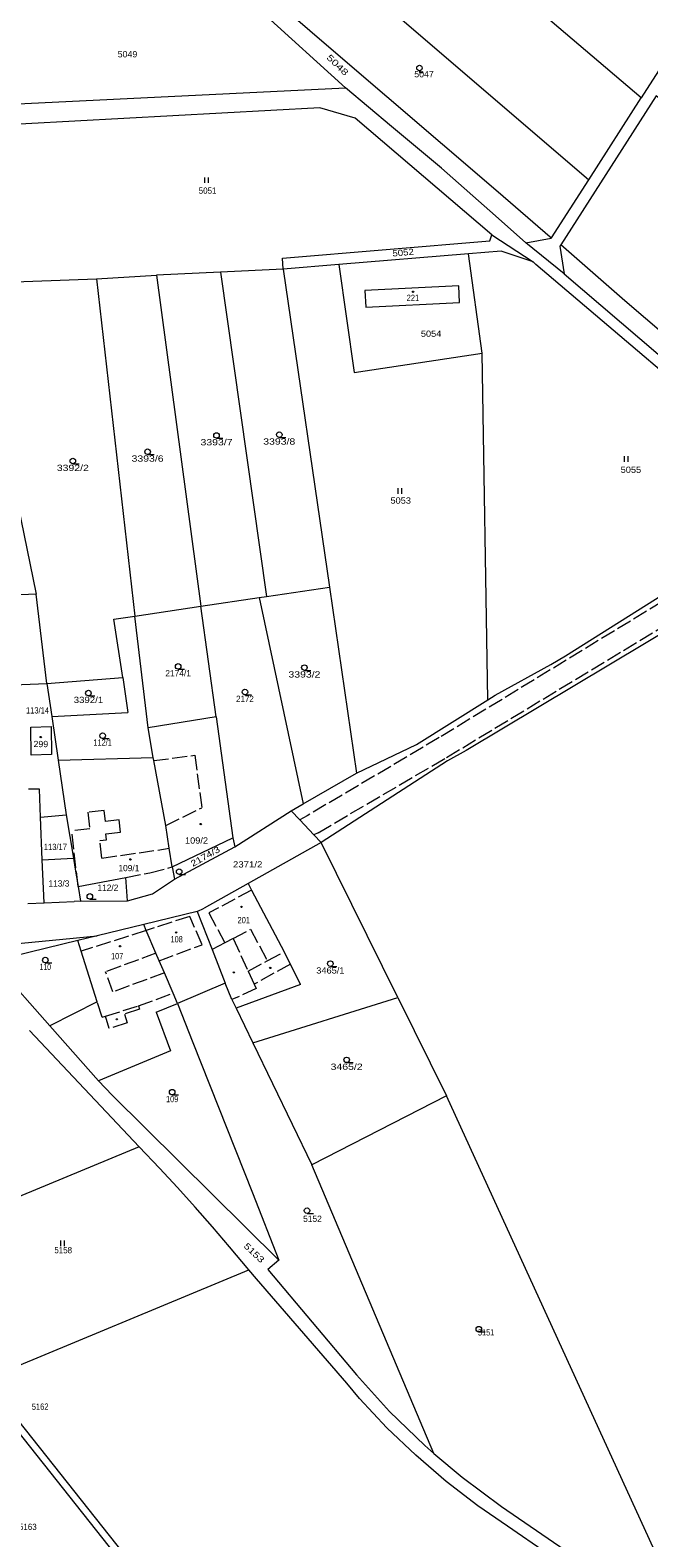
# Model space of a CAD drawing. Extents: x -590528 to -586543, y -1119609 to -1116685.
# Drawn here: x -588531 to -588363.1, y -1118530.4 to -1118121.8 of the extents above; entities that cross this region are included whole.
import ezdxf
from ezdxf.enums import TextEntityAlignment as Align

# ---------------------------------------------------------------- set-up
doc = ezdxf.new("R2010")
doc.units = 0
doc.header["$LTSCALE"] = 0.68
doc.linetypes.add('LONG_DASHED', pattern=[7.5, 6, -1.5])
for name, color, linetype, lineweight in [('1', 7, 'Continuous', 13), ('2', 7, 'LONG_DASHED', 13), ('3', 7, 'Continuous', 13), ('6', 7, 'Continuous', 13)]:
    doc.layers.add(name, color=color, linetype=linetype, lineweight=lineweight)

msp = doc.modelspace()

# ---------------------------------------------------------------- linework, layer by layer
at = {"layer": '1'}
for p, q in [((-588306.86, -1118049.02), (-588365.16, -1118140.1)), ((-588365.16, -1118140.1), (-588458.27, -1118060.91)), ((-588463.5, -1118090.17), (-588379.4, -1118162.35)), ((-588445.35, -1118137.46), (-588467.73, -1118117.14)), ((-588562.14, -1118143.12), (-588445.35, -1118137.46)), ((-588432.86, -1118147.9), (-588445.35, -1118137.46)), ((-588379.4, -1118162.35), (-588365.16, -1118140.1)), ((-588405.64, -1118177.25), (-588442.78, -1118145.68)), ((-588403.93, -1118165.64), (-588389.82, -1118177.8)), ((-588405.64, -1118177.25), (-588394.44, -1118184.61)), ((-588386.08, -1118187.86), (-588396.42, -1118179.44)), ((-588479.32, -1118187.36), (-588466.79, -1118275.29)), ((-588447.22, -1118185.31), (-588462.32, -1118186.55)), ((-588462.32, -1118186.55), (-588449.74, -1118272.77)), ((-588512.93, -1118189.15), (-588496.67, -1118188.18)), ((-588512.93, -1118189.15), (-588502.58, -1118280.59)), ((-588496.67, -1118188.18), (-588484.64, -1118277.93)), ((-588406.8, -1118303.29), (-588408.31, -1118209.31)), ((-588534.32, -1118250.35), (-588529.35, -1118274.66)), ((-588529.35, -1118274.66), (-588568.79, -1118276.37)), ((-588526.42, -1118298.88), (-588529.35, -1118274.66)), ((-588468.82, -1118275.59), (-588456.87, -1118331.51)), ((-588480.5, -1118307.9), (-588484.64, -1118277.93)), ((-588350.37, -1118279.8), (-588412.67, -1118317.05)), ((-588526.42, -1118298.88), (-588505.84, -1118297.29)), ((-588505.84, -1118297.29), (-588504.42, -1118306.75)), ((-588526.42, -1118298.88), (-588525.11, -1118307.78)), ((-588525.11, -1118307.78), (-588504.42, -1118306.75)), ((-588525.11, -1118307.78), (-588523.38, -1118319.65)), ((-588480.5, -1118307.9), (-588475.97, -1118340.68)), ((-588530.66, -1118318.29), (-588530.75, -1118310.67)), ((-588497.59, -1118318.95), (-588498.89, -1118310.86)), ((-588525.16, -1118318.1), (-588530.66, -1118318.29)), ((-588412.67, -1118317.05), (-588417.72, -1118319.86)), ((-588523.38, -1118319.65), (-588497.59, -1118318.95)), ((-588523.38, -1118319.65), (-588521.18, -1118334.51)), ((-588417.72, -1118319.86), (-588452.02, -1118342.01)), ((-588456.87, -1118331.51), (-588442.39, -1118323.14)), ((-588528.46, -1118327.49), (-588531.44, -1118327.55)), ((-588475.44, -1118343.19), (-588460.12, -1118333.39)), ((-588460.12, -1118333.39), (-588456.87, -1118331.51)), ((-588460.12, -1118333.39), (-588457.79, -1118335.87)), ((-588493.2, -1118343.55), (-588494.13, -1118337.39)), ((-588457.79, -1118335.87), (-588453.97, -1118339.94)), ((-588492.43, -1118348.6), (-588475.97, -1118340.68)), ((-588475.97, -1118340.68), (-588475.44, -1118343.19)), ((-588453.97, -1118339.94), (-588452.02, -1118342.01)), ((-588431.15, -1118384.02), (-588452.02, -1118342.01)), ((-588527.67, -1118346.7), (-588519.23, -1118346.22)), ((-588527.19, -1118358.3), (-588527.67, -1118346.7)), ((-588492.43, -1118348.6), (-588493.2, -1118343.55)), ((-588491.8, -1118351.95), (-588475.44, -1118343.19)), ((-588518.83, -1118348.62), (-588517.95, -1118353.91)), ((-588492.43, -1118348.6), (-588491.8, -1118351.95)), ((-588517.95, -1118353.91), (-588505.03, -1118351.45)), ((-588504.56, -1118357.77), (-588505.03, -1118351.45)), ((-588497.78, -1118355.9), (-588491.8, -1118351.95)), ((-588471.83, -1118353.1), (-588470.87, -1118354.91)), ((-588470.87, -1118354.91), (-588462.02, -1118371.6)), ((-588517.29, -1118357.9), (-588518.99, -1118357.97)), ((-588504.56, -1118357.77), (-588497.78, -1118355.9)), ((-588485.61, -1118360.7), (-588500.14, -1118364.23)), ((-588485.61, -1118360.7), (-588483.71, -1118359.75)), ((-588485.61, -1118360.7), (-588481.59, -1118371.02)), ((-588544.65, -1118370.34), (-588512.81, -1118367.3)), ((-588518.04, -1118368.57), (-588541.12, -1118374.2)), ((-588517.13, -1118371.44), (-588518.04, -1118368.57)), ((-588512.79, -1118385.12), (-588517.13, -1118371.44)), ((-588481.59, -1118371.02), (-588478.06, -1118380.09)), ((-588541.12, -1118374.2), (-588525.61, -1118391.67)), ((-588460.34, -1118374.98), (-588462.02, -1118371.6)), ((-588457.62, -1118380.46), (-588460.34, -1118374.98)), ((-588490.96, -1118385.61), (-588492.15, -1118382.84)), ((-588457.62, -1118380.46), (-588475.09, -1118386.9)), ((-588512.79, -1118385.12), (-588525.61, -1118391.67)), ((-588496.73, -1118387.95), (-588490.96, -1118385.61)), ((-588476.23, -1118384.56), (-588475.09, -1118386.9)), ((-588431.15, -1118384.02), (-588417.94, -1118410.63)), ((-588525.61, -1118391.67), (-588512.39, -1118406.56)), ((-588531.17, -1118392.89), (-588501.37, -1118424.43)), ((-588486.77, -1118396.19), (-588470.63, -1118436.94)), ((-588470.55, -1118396.26), (-588454.52, -1118429.35)), ((-588508.68, -1118410.46), (-588512.39, -1118406.56)), ((-588463.48, -1118455.16), (-588508.68, -1118410.46)), ((-588417.94, -1118410.63), (-588454.52, -1118429.35)), ((-588354.11, -1118550.09), (-588417.94, -1118410.63)), ((-588470.63, -1118436.94), (-588463.48, -1118455.16)), ((-588544.44, -1118488.93), (-588490.36, -1118556.97)), ((-588492.66, -1118550.88), (-588543.11, -1118487.4)), ((-588421.41, -1118507.55), (-588413.75, -1118514.03)), ((-588413.75, -1118514.03), (-588403.05, -1118521.93))]:
    msp.add_line(p, q, dxfattribs=at)
for points in [[(-588467.28, -1118111.3), (-588449.24, -1118126.81), (-588403.93, -1118165.64)], [(-588273.64, -1118212.52), (-588361.09, -1118139.58), (-588386.98, -1118180.02)], [(-588442.78, -1118145.68), (-588452.37, -1118142.81), (-588545.5, -1118147.9)], [(-588396.42, -1118179.44), (-588404.65, -1118172.16), (-588419.38, -1118159.23), (-588432.86, -1118147.9)], [(-588389.82, -1118177.8), (-588389.47, -1118178.07), (-588379.4, -1118162.35)], [(-588462.32, -1118186.55), (-588462.46, -1118183.55), (-588406.2, -1118178.91), (-588405.64, -1118177.25)], [(-588396.42, -1118179.44), (-588389.55, -1118178.2), (-588389.47, -1118178.07)], [(-588394.44, -1118184.61), (-588403.13, -1118181.67), (-588412.04, -1118182.4)], [(-588317.69, -1118239.25), (-588322.95, -1118234.85), (-588342.23, -1118218.58), (-588369.57, -1118195.12), (-588386.98, -1118180.02), (-588387.2, -1118180.36), (-588386.08, -1118187.86), (-588330.07, -1118235.65), (-588326.39, -1118238.65)], [(-588462.32, -1118186.55), (-588479.32, -1118187.36), (-588496.67, -1118188.18)], [(-588332.01, -1118237.68), (-588393.7, -1118185.27), (-588394.44, -1118184.61)], [(-588540.83, -1118187.61), (-588540.17, -1118190.18), (-588512.93, -1118189.15)], [(-588389.65, -1118293.69), (-588385.67, -1118291.34), (-588328.77, -1118255.57)], [(-588468.82, -1118275.59), (-588466.79, -1118275.29), (-588449.74, -1118272.77), (-588442.39, -1118323.14)], [(-588505.84, -1118297.29), (-588508.23, -1118281.43), (-588502.58, -1118280.59), (-588484.64, -1118277.93), (-588468.82, -1118275.59)], [(-588480.5, -1118307.9), (-588498.89, -1118310.86), (-588502.58, -1118280.59)], [(-588442.39, -1118323.14), (-588426.09, -1118315.45), (-588406.8, -1118303.29), (-588404.76, -1118302), (-588389.65, -1118293.69)], [(-588555.73, -1118299.98), (-588548.3, -1118299.69), (-588540.24, -1118299.39), (-588533.24, -1118299.13), (-588526.42, -1118298.88)], [(-588530.75, -1118310.67), (-588525.23, -1118310.52), (-588525.16, -1118318.1)], [(-588494.13, -1118337.39), (-588497.43, -1118319.79), (-588497.59, -1118318.95)], [(-588527.67, -1118346.7), (-588528.14, -1118335.08), (-588528.46, -1118327.49)], [(-588528.14, -1118335.08), (-588521.18, -1118334.51), (-588519.23, -1118346.22), (-588518.83, -1118348.62)], [(-588452.02, -1118342.01), (-588471.83, -1118353.1), (-588483.71, -1118359.75)], [(-588517.95, -1118353.91), (-588517.29, -1118357.9), (-588504.56, -1118357.77)], [(-588531.56, -1118358.48), (-588527.19, -1118358.3), (-588518.99, -1118357.97)], [(-588499.45, -1118365.83), (-588500.14, -1118364.23), (-588512.81, -1118367.3), (-588518.04, -1118368.57)], [(-588495.92, -1118374.06), (-588496.81, -1118371.98), (-588499.45, -1118365.83)], [(-588492.15, -1118382.84), (-588494.52, -1118377.32), (-588495.92, -1118374.06)], [(-588476.23, -1118384.56), (-588478.06, -1118380.09), (-588490.96, -1118385.61), (-588486.77, -1118396.19)], [(-588475.09, -1118386.9), (-588470.55, -1118396.26), (-588431.15, -1118384.02)], [(-588496.73, -1118387.95), (-588492.9, -1118398.44), (-588512.39, -1118406.56)], [(-588501.37, -1118424.43), (-588569.89, -1118452.8), (-588586.49, -1118433.03)], [(-588543.11, -1118487.4), (-588471.59, -1118457.8), (-588476.86, -1118451.54), (-588481.49, -1118446.13), (-588486.19, -1118440.78), (-588490.97, -1118435.5), (-588495.83, -1118430.28), (-588501.37, -1118424.43)], [(-588433.45, -1118496.17), (-588423.9, -1118505.43), (-588421.41, -1118507.55), (-588454.52, -1118429.35)], [(-588463.48, -1118455.16), (-588466.46, -1118457.67), (-588442.36, -1118486.29), (-588433.45, -1118496.17)], [(-588418.08, -1118515.14), (-588426.3, -1118508.08), (-588434.13, -1118500.59), (-588441.55, -1118492.69), (-588445.01, -1118488.5), (-588469.51, -1118460.25), (-588471.59, -1118457.8)], [(-588403.05, -1118521.93), (-588379.49, -1118538.12), (-588366.48, -1118545.6), (-588361.01, -1118548.5), (-588355.05, -1118550.07), (-588354.11, -1118550.09), (-588348.89, -1118550.23), (-588342.86, -1118548.98), (-588328.2, -1118545.4), (-588227.19, -1118511.98)], [(-588401.4, -1118527.28), (-588409.5, -1118521.75), (-588418.08, -1118515.14)], [(-588226.11, -1118515.22), (-588341.38, -1118553.44), (-588344.14, -1118554.35), (-588349.91, -1118555.14), (-588355.73, -1118554.85), (-588361.39, -1118553.51), (-588366.71, -1118551.14), (-588369.11, -1118549.5), (-588401.4, -1118527.28)]]:
    msp.add_lwpolyline(points, dxfattribs=at)
for points in [[(-588408.31, -1118209.31), (-588412.04, -1118182.4), (-588447.22, -1118185.31), (-588443.02, -1118214.61)], [(-588414.67, -1118191.08), (-588440.13, -1118192.33), (-588439.91, -1118196.84), (-588414.45, -1118195.6)]]:
    msp.add_lwpolyline(points, close=True, dxfattribs=at)
at = {"layer": '2'}
for p, q in [((-588497.43, -1118319.79), (-588486.28, -1118318.33)), ((-588486.28, -1118318.33), (-588484.37, -1118332.54)), ((-588510.84, -1118333.27), (-588515.31, -1118333.77)), ((-588515.31, -1118333.77), (-588514.8, -1118338.25)), ((-588510.5, -1118336.25), (-588510.84, -1118333.27)), ((-588494.13, -1118337.39), (-588484.37, -1118332.54)), ((-588455.77, -1118334.72), (-588457.79, -1118335.87)), ((-588514.8, -1118338.25), (-588519.67, -1118338.8)), ((-588517.95, -1118353.91), (-588519.67, -1118338.8)), ((-588506.82, -1118335.83), (-588510.5, -1118336.25)), ((-588506.44, -1118339.21), (-588506.82, -1118335.83)), ((-588512.02, -1118341.45), (-588510.23, -1118341.25)), ((-588511.48, -1118346.22), (-588512.02, -1118341.45)), ((-588510.41, -1118339.66), (-588506.44, -1118339.21)), ((-588510.23, -1118341.25), (-588510.41, -1118339.66)), ((-588452.81, -1118339.31), (-588453.97, -1118339.94)), ((-588511.48, -1118346.22), (-588493.2, -1118343.55)), ((-588505.03, -1118351.45), (-588498.51, -1118350.21)), ((-588498.51, -1118350.21), (-588492.43, -1118348.6)), ((-588470.87, -1118354.91), (-588482.44, -1118361.04)), ((-588484.3, -1118369.68), (-588487.64, -1118361.99)), ((-588482.44, -1118361.04), (-588478.13, -1118369.17)), ((-588475.88, -1118367.97), (-588471.16, -1118365.47)), ((-588495.92, -1118374.06), (-588484.3, -1118369.68)), ((-588496.81, -1118371.98), (-588510.49, -1118377.01)), ((-588460.34, -1118374.98), (-588470.17, -1118380.37)), ((-588508.49, -1118382.45), (-588510.49, -1118377.01)), ((-588494.52, -1118377.32), (-588508.49, -1118382.45)), ((-588471.81, -1118376.82), (-588470.17, -1118380.37)), ((-588501.58, -1118386.23), (-588492.15, -1118382.84)), ((-588469.62, -1118381.57), (-588476.23, -1118384.56)), ((-588470.17, -1118380.37), (-588469.62, -1118381.57)), ((-588511.44, -1118389.36), (-588512.79, -1118385.12)), ((-588501.27, -1118387.19), (-588505.37, -1118388.49)), ((-588501.58, -1118386.23), (-588501.27, -1118387.19)), ((-588505.37, -1118388.49), (-588504.62, -1118390.87))]:
    msp.add_line(p, q, dxfattribs=at)
for points in [[(-588355.01, -1118273.98), (-588419.95, -1118313.55), (-588455.77, -1118334.72)], [(-588452.81, -1118339.31), (-588417.94, -1118318.91), (-588351.51, -1118278.77)], [(-588487.64, -1118361.99), (-588499.45, -1118365.83), (-588517.13, -1118371.44)], [(-588471.16, -1118365.47), (-588466.6, -1118374.04), (-588462.02, -1118371.6)], [(-588475.88, -1118367.97), (-588478.13, -1118369.17), (-588481.59, -1118371.02)], [(-588475.88, -1118367.97), (-588471.81, -1118376.82), (-588466.6, -1118374.04)], [(-588511.44, -1118389.36), (-588510.54, -1118389.07), (-588501.58, -1118386.23)], [(-588504.62, -1118390.87), (-588509.49, -1118392.41), (-588510.54, -1118389.07)]]:
    msp.add_lwpolyline(points, dxfattribs=at)
at = {"layer": '6'}
for p, q in [((-588483.52, -1118163.21), (-588483.52, -1118161.71)), ((-588482.52, -1118163.21), (-588482.52, -1118161.71)), ((-588480.38, -1118232.39), (-588478.63, -1118232.39)), ((-588463.36, -1118232.18), (-588461.61, -1118232.18)), ((-588519.37, -1118239.33), (-588517.62, -1118239.33)), ((-588499.09, -1118236.81), (-588497.34, -1118236.81)), ((-588369.72, -1118238.77), (-588369.72, -1118237.27)), ((-588368.72, -1118238.77), (-588368.72, -1118237.27)), ((-588431.09, -1118247.44), (-588431.09, -1118245.94)), ((-588430.09, -1118247.44), (-588430.09, -1118245.94)), ((-588490.8, -1118295), (-588489.05, -1118295)), ((-588456.53, -1118295.31), (-588454.78, -1118295.31)), ((-588472.67, -1118301.94), (-588470.92, -1118301.94)), ((-588515.14, -1118302.23), (-588513.39, -1118302.23)), ((-588511.29, -1118313.78), (-588509.54, -1118313.78)), ((-588490.52, -1118350.62), (-588488.77, -1118350.62)), ((-588514.75, -1118357.34), (-588513, -1118357.34)), ((-588526.84, -1118374.6), (-588525.09, -1118374.6)), ((-588449.49, -1118375.55), (-588447.74, -1118375.55)), ((-588445.08, -1118401.65), (-588443.33, -1118401.65)), ((-588492.42, -1118410.41), (-588490.67, -1118410.41)), ((-588455.83, -1118442.51), (-588454.08, -1118442.51)), ((-588522.6, -1118451.37), (-588522.6, -1118449.87)), ((-588521.6, -1118451.37), (-588521.6, -1118449.87)), ((-588409.22, -1118474.65), (-588407.47, -1118474.65))]:
    msp.add_line(p, q, dxfattribs=at)
msp.add_lwpolyline([(-588425.32, -1118132.8), (-588425.32, -1118133.3), (-588424.32, -1118133.3)], dxfattribs=at)
for centre, radius in [((-588425.32, -1118132.05), 0.75), ((-588427.0602, -1118192.6804), 0.175), ((-588480.38, -1118231.64), 0.75), ((-588463.36, -1118231.43), 0.75), ((-588499.09, -1118236.06), 0.75), ((-588519.37, -1118238.58), 0.75), ((-588490.8, -1118294.25), 0.75), ((-588456.53, -1118294.56), 0.75), ((-588515.14, -1118301.48), 0.75), ((-588472.67, -1118301.19), 0.75), ((-588528.0802, -1118313.3904), 0.175), ((-588511.29, -1118313.03), 0.75), ((-588484.6602, -1118336.9804), 0.175), ((-588503.7502, -1118346.5604), 0.175), ((-588490.52, -1118349.87), 0.75), ((-588514.75, -1118356.59), 0.75), ((-588473.6002, -1118359.4404), 0.175), ((-588491.3302, -1118366.3304), 0.175), ((-588506.5602, -1118370.1104), 0.175), ((-588526.84, -1118373.85), 0.75), ((-588449.49, -1118374.8), 0.75), ((-588475.6902, -1118377.1704), 0.175), ((-588465.8102, -1118375.9604), 0.175), ((-588507.4402, -1118389.9004), 0.175), ((-588445.08, -1118400.9), 0.75), ((-588492.42, -1118409.66), 0.75), ((-588455.83, -1118441.76), 0.75), ((-588409.22, -1118473.9), 0.75)]:
    msp.add_circle(centre, radius, dxfattribs=at)

# ---------------------------------------------------------------- texts
at = {"layer": '3'}
for s, width, p in [('5049', 1.05, (-588507.193, -1118129.16)), ('5047', 1.05, (-588426.733, -1118134.57)), ('5051', 0.95, (-588485.213, -1118166.13)), ('221', 0.9, (-588428.803, -1118195.19)), ('5054', 1.1, (-588424.943, -1118204.91)), ('5055', 1.1, (-588370.723, -1118241.78)), ('5053', 1.1, (-588433.183, -1118250.13)), ('5158', 0.95, (-588524.383, -1118453.32)), ('5151', 0.8, (-588409.433, -1118475.6)), ('5162', 0.9, (-588530.523, -1118495.74)), ('5163', 0.95, (-588533.973, -1118528.31))]:
    msp.add_text(s, height=1.7, dxfattribs=dict(at, width=width)).set_placement(p)
for s, rotation, width, p in [('5048', 316.158, 1.4, (-588450.679, -1118129.394)), ('5052', 4.698, 1.15, (-588432.583, -1118183.151)), ('5153', 316.502, 1.3, (-588473.148, -1118451.553))]:
    msp.add_text(s, height=1.7, rotation=rotation, dxfattribs=dict(at, width=width)).set_placement(p)
for s, width, p in [('3393/7', 1.25, (-588480.38, -1118234.34)), ('3393/8', 1.25, (-588463.3605, -1118234.13)), ('3392/2', 1.25, (-588519.3705, -1118241.28)), ('3393/6', 1.25, (-588499.0905, -1118238.76)), ('3393/2', 1.25, (-588456.53, -1118297.26)), ('113/14', 0.9, (-588528.96, -1118307.01)), ('3392/1', 1.15, (-588515.14, -1118304.18)), ('2172', 0.95, (-588472.6705, -1118303.89)), ('112/1', 0.85, (-588511.2905, -1118315.73)), ('299', 1.05, (-588528.0505, -1118316.13)), ('113/17', 0.9, (-588524.1, -1118344.02)), ('109/2', 1.1, (-588485.811, -1118342.28)), ('2371/2', 1.15, (-588471.9305, -1118348.75)), ('201', 0.9, (-588472.9905, -1118363.85)), ('108', 0.85, (-588491.21, -1118369.06)), ('110', 0.65, (-588526.8405, -1118376.55)), ('107', 0.85, (-588507.3405, -1118373.61)), ('3465/1', 1.1, (-588449.49, -1118377.5)), ('3465/2', 1.25, (-588445.0805, -1118403.6)), ('109', 0.85, (-588492.4205, -1118412.36))]:
    msp.add_text(s, height=1.7, dxfattribs=dict(at, width=width)).set_placement(p, align=Align.CENTER)
for s, p in [('2174/1', (-588490.8005, -1118296.95)), ('109/1', (-588504.1605, -1118349.75)), ('113/3', (-588523.15, -1118353.92)), ('112/2', (-588509.86, -1118355.08))]:
    msp.add_text(s, height=1.7, dxfattribs=at).set_placement(p, align=Align.CENTER)
at = {"layer": '3', "width": 1.25}
msp.add_text('2174/3', height=1.7, rotation=29.45, dxfattribs=at).set_placement((-588483.0129, -1118346.4843), align=Align.CENTER)
at = {"layer": '3'}
msp.add_text('5152', height=1.7, dxfattribs=at).set_placement((-588456.873, -1118444.81))

doc.saveas('drawing.dxf')
